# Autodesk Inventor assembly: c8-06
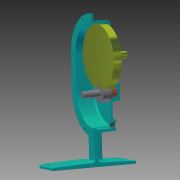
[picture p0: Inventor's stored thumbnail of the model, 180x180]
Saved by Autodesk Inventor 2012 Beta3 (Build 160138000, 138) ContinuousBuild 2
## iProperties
Created: 2010-12
Part Number: c8-06
Document SubType Name: Assembly
Designer: Thom Tremblay
Author: Thom Tremblay
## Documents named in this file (5)
- C:\Inventor 2012 Essentials\Assemblies\Chapter 8\c8-06.iam
- C:\Inventor 2012 Essentials\Content Center Files\en-US\ISO 2795  F\ISO 2795 - 10 x 14 x 10F.ipt
- C:\Inventor 2012 Essentials\Parts\Chapter 8\c8-11.ipt
- C:\Inventor 2012 Essentials\Assemblies\Chapter 8\Design Accelerators\Blank Input Shaft 2.iam
- C:\Inventor 2012 Essentials\Assemblies\Chapter 8\Design Accelerators\Blank Transfer Shaft.iam
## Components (5 placed, 4 different names)
1. c8-11:1 — Insert:27, Insert:28
2. ISO 2795 (Flanged) 10 x 14 x 10:2 — Insert:27, Insert:30
3. ISO 2795 (Flanged) 10 x 14 x 10:3 — Insert:28, Insert:29
4. Blank Input Shaft 2:1 [sub-assembly] — Insert:29
5. Blank Transfer Shaft:1 [sub-assembly] — Insert:30
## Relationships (4: Insert 4)
- Insert:27: c8-11:1 ↔ ISO 2795 (Flanged) 10 x 14 x 10:2
- Insert:28: c8-11:1 ↔ ISO 2795 (Flanged) 10 x 14 x 10:3
- Insert:29: ISO 2795 (Flanged) 10 x 14 x 10:3 ↔ Blank Input Shaft 2:1
- Insert:30: ISO 2795 (Flanged) 10 x 14 x 10:2 ↔ Blank Transfer Shaft:1
